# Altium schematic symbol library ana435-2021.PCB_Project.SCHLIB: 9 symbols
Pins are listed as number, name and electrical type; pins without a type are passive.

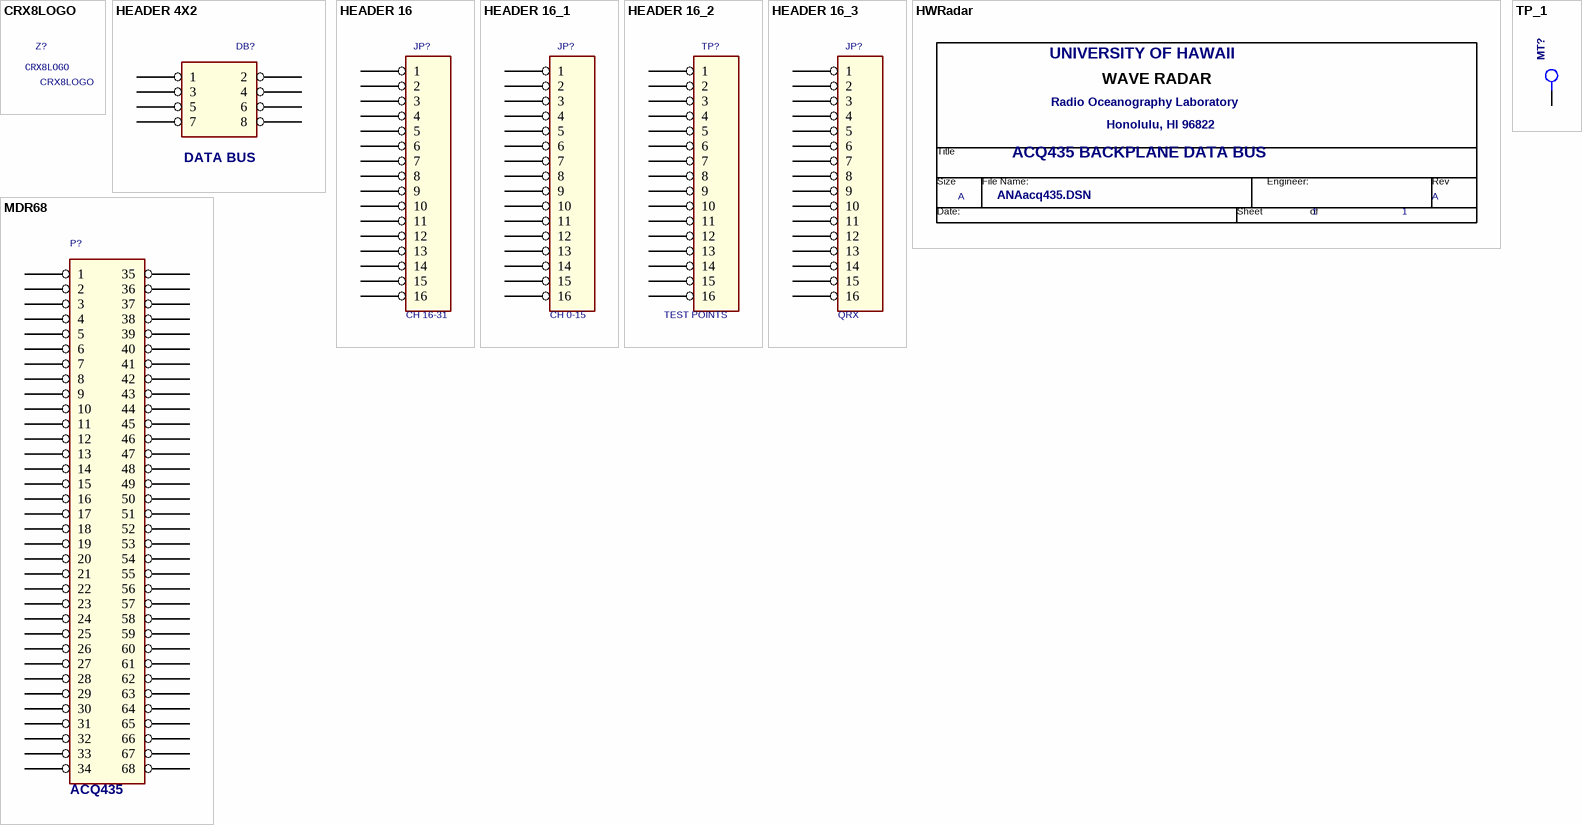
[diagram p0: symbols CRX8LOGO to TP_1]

## CRX8LOGO
designator Z?
MFR PART: DNI
footprint CRX8TINY

## HEADER 4X2
designator DB?, comment DATA BUS
MFR: Samtec; MFR PART: SSW-104-02-G-D-RA; DK Stock: SAM1215-04-ND
footprint TSW-4X2F
pins: 1, 2, 3, 4, 5, 6, 7, 8

## HEADER 16
designator JP?, comment CH 16-31
MFR: TE Connectivity; MFR PART: 1-534237-4; DK Stock: A26426-ND
footprint SIP16
pins: 1, 2, 3, 4, 5, 6, 7, 8, 9, 10, 11, 12, 13, 14, 15, 16

## HEADER 16_1
designator JP?, comment CH 0-15
MFR: TE Connectivity; MFR PART: 1-534237-4; DK Stock: A26426-ND
footprint SIP16
pins: 1, 2, 3, 4, 5, 6, 7, 8, 9, 10, 11, 12, 13, 14, 15, 16

## HEADER 16_2
designator TP?, comment TEST POINTS
MFR PART: DNI
footprint SIP16
pins: 1, 2, 3, 4, 5, 6, 7, 8, 9, 10, 11, 12, 13, 14, 15, 16

## HEADER 16_3
designator JP?, comment QRX
MFR: TE Connectivity; MFR PART: 1-534237-4; DK Stock: A26426-ND
footprint SIP16
pins: 1, 2, 3, 4, 5, 6, 7, 8, 9, 10, 11, 12, 13, 14, 15, 16

## HWRadar
designator *?  Page Count: 1  Page Size: A  OrgAddr3: Honolulu, HI 96822  OrgAddr1: Radio Oceanography Laboratory  OrgName: UNIVERSITY OF HAWAII  Title: ACQ435 BACKPLANE DATA BUS  Doc: ANAacq435.DSN  (hidden comment: HWRadar)  (graphical)
OrgAddr2: 2525 Correa Road; Engineer:: <ENG>

## MDR68
designator P?, comment ACQ435
MFR: Molex; MFR PART: 737760201; DK Stock: WM7304-ND
footprint MDR68
footprint VHDCI-SMT
pins: 1, 2, 3, 4, 5, 6, 7, 8, 9, 10, 11, 12, 13, 14, 15, 16, 17, 18, 19, 20, 21, 22, 23, 24, 25, 26, 27, 28, 29, 30, 31, 32, 33, 34, 35, 36, 37, 38, 39, 40, 41, 42, 43, 44, 45, 46, 47, 48, 49, 50, 51, 52, 53, 54, 55, 56, 57, 58, 59, 60, 61, 62, 63, 64, 65, 66, 67, 68

## TP_1
designator MT?, comment GND  (value not drawn)
DK Stock: DNI
footprint TP
footprint MOUNT-3.5
pins: 1 TP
